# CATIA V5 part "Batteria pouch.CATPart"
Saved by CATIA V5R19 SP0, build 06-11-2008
Part number: Batteria pouch
Bounding box of the stored display mesh (mm): x -44.465 to -10.465, y -1.2 to 8.8, z -1.903 to 49.097
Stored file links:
  C:\Users\sisca\Desktop\HELTEC_CASE\Batteria pouch.CATPart
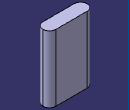
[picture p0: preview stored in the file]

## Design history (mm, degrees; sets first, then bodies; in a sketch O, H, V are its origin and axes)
Set1
  Plane1: stored without definition
Body1 (main body)
  Sketch1 on Plane1, origin (0, -1.2, 0), H (-1, 0, 0), V (0, 0, 1)
    line L1 (10.4653, 49.0965) -> (44.4653, 49.0965)
    line L2 (44.4653, 49.0965) -> (44.4653, -1.9035)
    line L3 (44.4653, -1.9035) -> (10.4653, -1.9035)
    line L4 (10.4653, -1.9035) -> (10.4653, 49.0965)
    length L3 = 34
    distance L1 L3 = 51
    horizontal: L1 H, L3 H
    vertical: L2 V, L4 V
  Pad1: profile Sketch1, direction (0, 1, 0), length 10
  Fillet1: radius 5, on edge [start face of Pad1 | face of Pad1 from Sketch1.L2]; edge [face of Pad1 from Sketch1.L2 | end face of Pad1]; edge [start face of Pad1 | face of Pad1 from Sketch1.L4]; edge [face of Pad1 from Sketch1.L4 | end face of Pad1]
